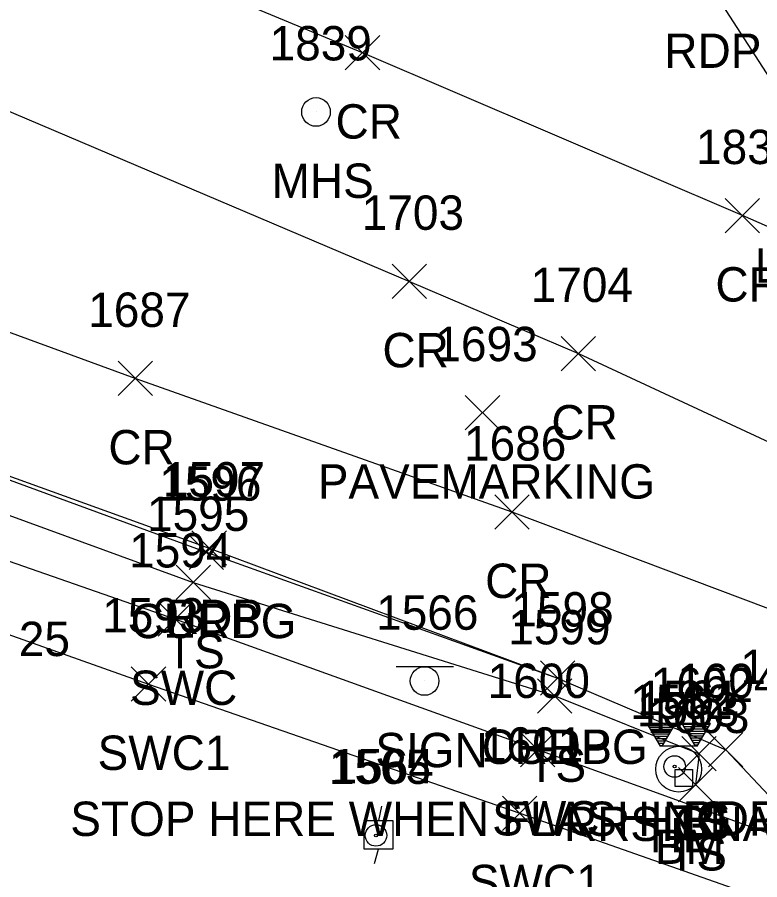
# Model space of a CAD drawing. Extents: x 1769141 to 1770817, y 735471 to 742405.
# Drawn here: x 1770149.9 to 1770193.1, y 741907.5 to 741957.6 of the extents above; entities that cross this region are included whole.
import ezdxf

# ---------------------------------------------------------------- set-up
doc = ezdxf.new("R2010")
doc.units = 0
for name, color, linetype in [('C_A', 7, 'Continuous'), ('C_I', 7, 'Continuous'), ('CBP', 7, 'Continuous'), ('CPBM', 7, 'Continuous'), ('L_A', 7, 'Continuous'), ('L_C', 7, 'Continuous'), ('L_I', 7, 'Continuous'), ('L_TIC', 7, 'Continuous'), ('LELB', 7, 'Continuous'), ('P_A', 7, 'Continuous'), ('P_I', 7, 'Continuous'), ('P_TIC', 7, 'Continuous'), ('PET', 7, 'Continuous'), ('PRC', 7, 'Continuous'), ('R_A', 7, 'Continuous'), ('R_I', 7, 'Continuous'), ('R_TIC', 7, 'Continuous'), ('RC', 7, 'Continuous'), ('RSW', 7, 'Continuous'), ('S_A', 7, 'Continuous'), ('S_C', 7, 'Continuous'), ('S_I', 7, 'Continuous'), ('S_TIC', 7, 'Continuous'), ('SSGN', 7, 'Continuous'), ('TCSH', 7, 'Continuous'), ('U_A', 7, 'Continuous'), ('U_I', 7, 'Continuous'), ('ULP', 7, 'Continuous'), ('USMH', 7, 'Continuous')]:
    doc.layers.add(name, color=color, linetype=linetype)

msp = doc.modelspace()

# ---------------------------------------------------------------- linework, layer by layer
at = {"layer": 'CBP'}
for centre, radius in [((1770188.129, 741914.042), 0.625), ((1770188.129, 741914.042), 0.0833), ((1770170.752, 741910.03), 0.625), ((1770170.752, 741910.03), 0.0833)]:
    msp.add_circle(centre, radius, dxfattribs=at)
at = {"layer": 'CPBM'}
for p, q in [((1770188.168, 741912.872), (1770188.168, 741913.872)), ((1770188.168, 741913.872), (1770189.168, 741913.872)), ((1770189.168, 741913.872), (1770189.168, 741912.872)), ((1770188.671, 741913.373), (1770188.671, 741913.373)), ((1770188.671, 741913.373), (1770188.671, 741913.373)), ((1770189.168, 741912.872), (1770188.168, 741912.872))]:
    msp.add_line(p, q, dxfattribs=at)
at = {"layer": 'L_TIC'}
for points in [[(1770159.124, 741923.753), (1770161.124, 741925.753)], [(1770161.124, 741923.753), (1770159.124, 741925.753)], [(1770180.152, 741917.15), (1770182.152, 741919.15)], [(1770182.152, 741917.15), (1770180.152, 741919.15)], [(1770188.55, 741913.788), (1770190.55, 741915.788)], [(1770190.55, 741913.788), (1770188.55, 741915.788)], [(1770188.347, 741911.989), (1770190.347, 741913.989)], [(1770190.347, 741911.989), (1770188.347, 741913.989)]]:
    msp.add_lwpolyline(points, dxfattribs=at)
at = {"layer": 'LELB'}
msp.add_lwpolyline([(1770097.493, 741946.924), (1770100.933, 741948.468), (1770115.47, 741941.089), (1770133.4, 741934.511), (1770160.124, 741924.753), (1770181.152, 741918.15), (1770189.55, 741914.788), (1770189.347, 741912.989)], dxfattribs=at)
at = {"layer": 'P_TIC'}
for points in [[(1770168.968, 741954.582), (1770170.968, 741956.582)], [(1770170.968, 741954.582), (1770168.968, 741956.582)], [(1770191.069, 741945.101), (1770193.069, 741947.101)], [(1770193.069, 741945.101), (1770191.069, 741947.101)], [(1770171.695, 741941.274), (1770173.695, 741943.274)], [(1770173.695, 741941.274), (1770171.695, 741943.274)], [(1770181.527, 741937.075), (1770183.527, 741939.075)], [(1770183.527, 741937.075), (1770181.527, 741939.075)], [(1770155.75, 741935.625), (1770157.75, 741937.625)], [(1770157.75, 741935.625), (1770155.75, 741937.625)], [(1770177.671, 741927.849), (1770179.671, 741929.849)], [(1770179.671, 741927.849), (1770177.671, 741929.849)], [(1770160.047, 741925.755), (1770162.047, 741927.755)], [(1770162.047, 741925.755), (1770160.047, 741927.755)], [(1770180.322, 741918.19), (1770182.322, 741920.19)], [(1770182.322, 741918.19), (1770180.322, 741920.19)], [(1770190.098, 741914.021), (1770192.098, 741916.021)], [(1770192.098, 741914.021), (1770190.098, 741916.021)]]:
    msp.add_lwpolyline(points, dxfattribs=at)
at = {"layer": 'PET'}
for points in [[(1770103.118, 742000.143), (1770127.081, 741989.314), (1770153.156, 741977.803), (1770175.529, 741967.595), (1770190.043, 741959.699), (1770195.581, 741951.123), (1770199.063, 741946.686), (1770205.336, 741942.729), (1770212.931, 741941.484), (1770218.09, 741938.93), (1770226.325, 741937.051), (1770234.75, 741938.385), (1770239.969, 741940.27), (1770247.113, 741944.112), (1770250.486, 741946.97), (1770254.108, 741952.371), (1770258.931, 741964.777), (1770264.961, 741993.489), (1770272.699, 742023.543), (1770282.638, 742061.023)], [(1770092.714, 741946.414), (1770094.596, 741949.858), (1770100.881, 741948.635), (1770116.302, 741942.755), (1770134.113, 741936.465), (1770161.047, 741926.755), (1770181.322, 741919.19), (1770191.098, 741915.021), (1770196.76, 741909.019), (1770195.729, 741905.489), (1770195.658, 741903.902), (1770198.168, 741903.041), (1770205.854, 741901.701), (1770208.168, 741901.359), (1770212.399, 741899.281), (1770224.424, 741895.692), (1770230.498, 741893.508), (1770238.482, 741890.555), (1770245.053, 741888.83), (1770266.408, 741881.651), (1770276.948, 741878.624), (1770295.844, 741873.498)]]:
    msp.add_lwpolyline(points, dxfattribs=at)
at = {"layer": 'PRC'}
for points in [[(1770287.044, 741911.42), (1770261.813, 741920.336), (1770242.525, 741926.853), (1770231.128, 741930.501), (1770222.527, 741933.201), (1770213.15, 741936.922), (1770207.451, 741939.591), (1770199.047, 741943.047), (1770192.069, 741946.101), (1770169.968, 741955.582), (1770146.029, 741965.505), (1770124.548, 741974.403), (1770095.916, 741986.431)], [(1770089.608, 741977.338), (1770111.169, 741968.202), (1770141.623, 741955.475), (1770172.695, 741942.274), (1770182.527, 741938.075), (1770200.015, 741929.956), (1770205.556, 741927.286), (1770211.15, 741924.407), (1770219.447, 741920.454), (1770228.602, 741916.999), (1770246.903, 741910.061), (1770272.504, 741900.23), (1770300.541, 741889.423), (1770310.207, 741885.753), (1770337.912, 741876.285), (1770361.623, 741867.868), (1770392.61, 741857.285), (1770418.497, 741848.782)], [(1770415.529, 741840.308), (1770384.051, 741850.541), (1770352.442, 741860.952), (1770318.836, 741870.925), (1770293.642, 741881.39), (1770273.131, 741889.105), (1770260.991, 741893.725), (1770236.986, 741901.134), (1770226.382, 741906.26), (1770214.294, 741912.937), (1770209.383, 741916.393), (1770203.96, 741918.649), (1770198.094, 741921.538), (1770178.671, 741928.849), (1770156.75, 741936.625), (1770131.368, 741945.922), (1770112.842, 741952.747), (1770098.759, 741957.002)]]:
    msp.add_lwpolyline(points, dxfattribs=at)
at = {"layer": 'R_TIC'}
for points in [[(1770159.887, 741925.511), (1770161.887, 741927.511)], [(1770161.887, 741925.511), (1770159.887, 741927.511)], [(1770158.083, 741921.624), (1770160.083, 741923.624)], [(1770160.083, 741921.624), (1770158.083, 741923.624)], [(1770156.516, 741917.842), (1770158.516, 741919.842)], [(1770158.516, 741917.842), (1770156.516, 741919.842)], [(1770180.322, 741918.19), (1770182.322, 741920.19)], [(1770182.322, 741918.19), (1770180.322, 741920.19)], [(1770179.154, 741914.03), (1770181.154, 741916.03)], [(1770181.154, 741914.03), (1770179.154, 741916.03)], [(1770178.116, 741910.322), (1770180.116, 741912.322)], [(1770180.116, 741910.322), (1770178.116, 741912.322)]]:
    msp.add_lwpolyline(points, dxfattribs=at)
at = {"layer": 'RC'}
msp.add_lwpolyline([(1770100.933, 741948.468), (1770116.152, 741942.59), (1770134.111, 741936.325), (1770160.887, 741926.511), (1770181.322, 741919.19)], dxfattribs=at)
at = {"layer": 'RSW'}
for points in [[(1770086.66, 741942.741), (1770086.604, 741947.314), (1770087.676, 741948.054), (1770092.714, 741946.414), (1770092.447, 741945.467), (1770100.235, 741943.049), (1770132.531, 741931.879), (1770159.083, 741922.624), (1770180.154, 741915.03), (1770196.76, 741909.019)], [(1770086.66, 741942.741), (1770091.237, 741941.943), (1770099.043, 741939.268), (1770131.132, 741928.211), (1770157.516, 741918.842), (1770179.116, 741911.322), (1770195.729, 741905.489)]]:
    msp.add_lwpolyline(points, dxfattribs=at)
at = {"layer": 'S_TIC'}
for points in [[(1770175.95, 741933.631), (1770177.95, 741935.631)], [(1770177.95, 741933.631), (1770175.95, 741935.631)]]:
    msp.add_lwpolyline(points, dxfattribs=at)
at = {"layer": 'SSGN'}
for p, q in [((1770171.931, 741919.853), (1770175.264, 741919.853)), ((1770173.578, 741919.019), (1770173.578, 741919.019))]:
    msp.add_line(p, q, dxfattribs=at)
msp.add_circle((1770173.578, 741919.019), 0.833, dxfattribs=at)
at = {"layer": 'TCSH'}
for p, q in [((1770188.177, 741916.55), (1770186.51, 741916.55)), ((1770186.51, 741916.55), (1770187.28, 741915.217)), ((1770187.407, 741915.217), (1770188.177, 741916.55)), ((1770190.212, 741916.55), (1770188.545, 741916.55)), ((1770188.545, 741916.55), (1770189.315, 741915.217)), ((1770189.442, 741915.217), (1770190.212, 741916.55)), ((1770189.442, 741915.217), (1770187.28, 741915.217)), ((1770188.361, 741913.884), (1770188.361, 741913.884))]:
    msp.add_line(p, q, dxfattribs=at)
for points in [[(1770186.555, 741916.474), (1770188.133, 741916.474)], [(1770186.632, 741916.341), (1770188.056, 741916.341)], [(1770186.708, 741916.207), (1770187.979, 741916.207)], [(1770188.573, 741916.502), (1770190.184, 741916.502)], [(1770188.65, 741916.369), (1770190.107, 741916.369)], [(1770188.727, 741916.236), (1770190.03, 741916.236)], [(1770186.785, 741916.074), (1770187.902, 741916.074)], [(1770186.862, 741915.941), (1770187.825, 741915.941)], [(1770186.939, 741915.807), (1770187.748, 741915.807)], [(1770188.804, 741916.102), (1770189.953, 741916.102)], [(1770188.881, 741915.969), (1770189.876, 741915.969)], [(1770188.958, 741915.836), (1770189.799, 741915.836)], [(1770189.035, 741915.702), (1770189.722, 741915.702)], [(1770187.016, 741915.674), (1770187.671, 741915.674)], [(1770187.093, 741915.541), (1770187.594, 741915.541)], [(1770187.17, 741915.407), (1770187.517, 741915.407)], [(1770187.247, 741915.274), (1770187.44, 741915.274)], [(1770189.112, 741915.569), (1770189.645, 741915.569)], [(1770189.189, 741915.436), (1770189.568, 741915.436)], [(1770189.266, 741915.302), (1770189.491, 741915.302)]]:
    msp.add_lwpolyline(points, dxfattribs=at)
msp.add_circle((1770188.361, 741913.884), 1.333, dxfattribs=at)
at = {"layer": 'ULP'}
for p, q in [((1770171.074, 741911.726), (1770170.908, 741910.892)), ((1770170.074, 741909.226), (1770170.074, 741910.892)), ((1770170.074, 741910.892), (1770171.741, 741910.892)), ((1770171.741, 741910.892), (1770171.741, 741909.226)), ((1770170.908, 741910.059), (1770170.908, 741910.059)), ((1770171.741, 741909.226), (1770170.074, 741909.226)), ((1770170.658, 741908.392), (1770170.908, 741909.226))]:
    msp.add_line(p, q, dxfattribs=at)
at = {"layer": 'USMH'}
for p, q in [((1770167.263, 741952.133), (1770167.263, 741952.133)), ((1770168.096, 741952.133), (1770168.096, 741952.133))]:
    msp.add_line(p, q, dxfattribs=at)
msp.add_circle((1770167.263, 741952.133), 0.833, dxfattribs=at)

# ---------------------------------------------------------------- texts
at = {"layer": 'C_A'}
for s, p in [('TIE', (1770186.208, 741909.042)), ('BM', (1770186.986, 741908.373))]:
    msp.add_text(s, height=2, dxfattribs=at).set_placement(p)
at = {"layer": 'C_I'}
for s, p in [('1561', (1770185.956, 741917.042)), ('1563', (1770185.931, 741916.373)), ('1565', (1770168.012, 741913.03))]:
    msp.add_text(s, height=2, dxfattribs=at).set_placement(p)
at = {"layer": 'L_A'}
for p in [(1770158.534, 741919.753), (1770179.561, 741913.15), (1770187.959, 741909.788), (1770187.756, 741907.989)]:
    msp.add_text('TS', height=2, dxfattribs=at).set_placement(p)
at = {"layer": 'L_C'}
msp.add_text('LANE ARROWS', height=2, dxfattribs=at).set_placement((1770192.791, 741942.2))
at = {"layer": 'L_I'}
for s, p in [('1595', (1770157.432, 741927.753)), ('1599', (1770178.451, 741921.15)), ('1602', (1770186.731, 741917.788)), ('1603', (1770186.528, 741915.989))]:
    msp.add_text(s, height=2, dxfattribs=at).set_placement(p)
at = {"layer": 'P_A'}
for s, p in [('RDP', (1770187.531, 741954.699)), ('CR', (1770168.401, 741950.582)), ('CR', (1770190.502, 741941.101)), ('CR', (1770171.128, 741937.274)), ('CR', (1770180.96, 741933.075)), ('CR', (1770155.183, 741931.625)), ('CR', (1770177.104, 741923.849)), ('RDP', (1770158.535, 741921.755)), ('RDP', (1770178.81, 741914.19)), ('RDP', (1770188.586, 741910.021))]:
    msp.add_text(s, height=2, dxfattribs=at).set_placement(p)
at = {"layer": 'P_I'}
for s, p in [('1837', (1770189.376, 741949.101)), ('1703', (1770169.923, 741945.274)), ('1704', (1770179.756, 741941.075)), ('1687', (1770154.01, 741939.625)), ('1686', (1770175.876, 741931.849)), ('1597', (1770158.354, 741929.755)), ('1598', (1770178.63, 741922.19)), ('1605', (1770191.951, 741918.835)), ('1604', (1770188.279, 741918.021))]:
    msp.add_text(s, height=2, dxfattribs=at).set_placement(p)
at = {"layer": 'R_A'}
for s, p in [('CURBG', (1770156.47, 741921.511)), ('SWC', (1770156.445, 741917.624)), ('CURBG', (1770176.905, 741914.19)), ('SWC1', (1770154.556, 741913.842)), ('SWC', (1770177.516, 741910.03)), ('RRSIGNAL', (1770181.687, 741909.706)), ('SWC1', (1770176.155, 741906.322))]:
    msp.add_text(s, height=2, dxfattribs=at).set_placement(p)
at = {"layer": 'R_I'}
for s, p in [('1596', (1770158.139, 741929.511)), ('1594', (1770156.39, 741925.624)), ('1598', (1770178.63, 741922.19)), ('1593', (1770154.824, 741921.842)), ('1600', (1770177.249, 741918.03)), ('1562', (1770185.546, 741916.806)), ('1601', (1770176.864, 741914.322))]:
    msp.add_text(s, height=2, dxfattribs=at).set_placement(p)
at = {"layer": 'S_A'}
for s, p in [('PAVEMARKING', (1770167.367, 741929.631)), ('SIGN', (1770170.716, 741913.999))]:
    msp.add_text(s, height=2, dxfattribs=at).set_placement(p)
at = {"layer": 'S_C'}
for s, p in [('SPEED LIMIT 25', (1770132.585, 741920.469)), ('STOP HERE WHEN FLASHING', (1770152.968, 741909.999))]:
    msp.add_text(s, height=2, dxfattribs=at).set_placement(p)
at = {"layer": 'S_I'}
for s, p in [('1693', (1770174.21, 741937.631)), ('1566', (1770170.763, 741921.999))]:
    msp.add_text(s, height=2, dxfattribs=at).set_placement(p)
at = {"layer": 'U_A'}
msp.add_text('MHS', height=2, dxfattribs=at).set_placement((1770164.68, 741947.133))
at = {"layer": 'U_I'}
for s, p in [('1839', (1770164.563, 741955.133)), ('1564', (1770168.168, 741913.059))]:
    msp.add_text(s, height=2, dxfattribs=at).set_placement(p)

doc.saveas('drawing.dxf')
